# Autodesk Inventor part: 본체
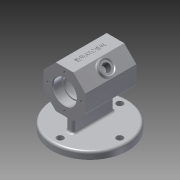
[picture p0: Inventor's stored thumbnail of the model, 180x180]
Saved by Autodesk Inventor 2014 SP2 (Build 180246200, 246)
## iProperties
Created: 2021-02
Part Number: 본체
Material: 알루미늄 6061
Document SubType Name: Modeling
Designer: 거성
Density: 2.71 g/cm^3
Appearance: 알루미늄 - 평지
Author: 거성
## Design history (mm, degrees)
sketch "스케치1"
  geometry: C1 r 52 at (0, 0); 1 further point
  constraints: 1 centre point, 1 coincident
  dimensions: "d0" = 104 diameter of C1
extrude "돌출1" new body sketch "스케치1" distance "d1" = 10; taper "d2" = 0 deg
sketch "스케치3"
  geometry: L1 (52, 10)-(-52, 10) reference; L2 (-52, 0)-(52, 0) reference; L3 (12.012, 33)-(-12.012, 33); L4 (-12.012, 33)-(-29, 49.988); L5 (-29, 49.988)-(-29, 74.012); L6 (-29, 74.012)-(-12.012, 91); L7 (-12.012, 91)-(12.012, 91); L8 (12.012, 91)-(29, 74.012); L9 (29, 74.012)-(29, 49.988); L10 (29, 49.988)-(12.012, 33); C1 r 29 at (0, 62); 3 further points
  constraints: 16 end point, 1 centre point, 1 coincident, 1 horizontal, 1 midpoint, 1 tangent, 1 vertical alignment, 17 other
  dimensions: "d12" = 58 diameter of C1; "d13" = 62 distance from line of L2 C1.centre
extrude "돌출2" join sketch "스케치3" stored distance "d14" = 70; taper "d15" = 0 deg
sketch "스케치4"
  geometry: L1 (49.988, 35)-(49.988, -35) reference; L2 (74.012, 35)-(49.988, 35) reference; L3 (74.012, 35)-(74.012, -35) reference; L4 (49.988, -35)-(74.012, -35) reference; L5 (74.012, 35)-(74.012, -35) reference; L6 (91, 35)-(74.012, 35) reference; L7 (91, 35)-(91, -35) reference; L8 (74.012, -35)-(91, -35) reference; L9 (33, 35)-(33, -35) reference; L10 (49.988, 35)-(33, 35) reference; L11 (49.988, 35)-(49.988, -35) reference; L12 (33, -35)-(49.988, -35) reference; L13 (10, -52)-(10, 52) reference; L14 (0, 52)-(0, -52) reference; L15 (62, 35)-(62, -35); L16 (62, 35)-(78, 35); L17 (78, 23)-(76, 23); L18 (76, 23)-(76, 20); L19 (76, 20)-(84, 20); L20 (84, 20)-(84, -20); L21 (84, -20)-(76, -20); L22 (76, -20)-(76, -23); L23 (76, -23)-(78, -23); L24 (78, -23)-(78, -35); L25 (78, 23)-(78, 35); L26 (78, -35)-(62, -35); 1 further point
  constraints: 24 end point, 4 collinear, 4 parallel, 3 perpendicular, 2 midpoint, 2 point on line, 1 horizontal
  dimensions: "d16" = 16 distance between parallel lines of L15 L25; "d17" = 3 distance between parallel lines of L19 L17; "d18" = 12 distance between parallel lines of L17 L16; "d19" = 14 distance between parallel lines of L15 L18; "d20" = 22 distance between parallel lines of L15 L20; "d21" = 40 distance between parallel lines of L21 L19; "d22" = 3 distance between parallel lines of L21 L23
revolve "회전1" sketch "스케치4" stored, may be unused: angle "d23" = 90 deg
sketch "스케치5"
  geometry: C1 r 52 at (0, 0) reference; C2 r 4.5 at (0, 41)
  constraints: 1 centre point, 1 vertical alignment
  dimensions: "d24" = 9 diameter of C2; "d25" = 41 distance of C1.centre C2.centre
extrude "돌출3" cut sketch "스케치5" stored distance "d26" = 70; taper "d27" = 0 deg
fillet "모깎기1" dims "d31" = 3
chamfer "모따기1" distance "d32" = 1; stored, may be unused: second distance "d33" = 2, angle "d34" = 45 deg
fillet "모깎기2" dims "d35" = 0.3
fillet "모깎기3" dims "d36" = 3
sketch "스케치6"
  geometry: C1 r 17 at (0, 62) reference; C2 r 2 at (0, 85); 1 further point
  constraints: 1 centre point, 1 vertical alignment
  dimensions: "d37" = 23 distance of C1.centre C2.centre; "d38" = 4 diameter of C2
hole "구멍1" sketch "스케치6" at (0, 85) diameter "d39" = 3.242; stored, may be unused: countersink angle "d43" = 90 deg, drill point angle "d45" = 118 deg; dims "d40" = 8, "d41" = 4, "d42" = 2, "d44" = 10
sketch "스케치7"
  geometry: L1 (24.024, 0)-(0, 0) reference; L2 (-16.988, 0)-(-16.988, 70) reference; 2 further points
  constraints: 1 other
  dimensions: "d49" = 29 distance from line of L2 point (12.012, 35); "d50" = 35 distance from line of L1 point (12.012, 35)
feature "엠보싱1" sketch "스케치7" dims "d1" = 10, "d2" = 0, "d51" = 0.5, "d52" = 0
sketch "스케치8"
  geometry: L1 (33, 35)-(33, -35) reference; L2 (49.988, 35)-(33, 35) reference; L3 (49.988, 35)-(49.988, -35) reference; L4 (33, -35)-(49.988, -35) reference; L5 (0, 52)-(0, -52) reference; L6 (7, -52)-(7, 52) reference; L7 (10, 49)-(10, -49) reference; L8 (7, -52)-(7, 52) reference; L9 (10, 49)-(10, -49) reference; L10 (33, 28)-(10, 28); L11 (10, 28)-(10, -28); L12 (10, -28)-(33, -28); L13 (33, -28)-(33, 28); 3 further points
  constraints: 8 end point, 2 collinear, 2 midpoint, 2 parallel, 1 horizontal, 1 horizontal alignment, 1 perpendicular
  dimensions: "d53" = 56 distance between parallel lines of L12 L10
extrude "돌출4" join sketch "스케치8" stored distance "d54" = 10; taper "d55" = 0 deg
fillet "모깎기4" dims "d56" = 3
fillet "모깎기5" dims "d57" = 3
sketch "스케치9"
  geometry: L1 (16.988, 70)-(16.988, 0) reference; C1 r 10 at (-12.012, 35); 1 further point
  constraints: 1 centre point, 1 horizontal alignment
  dimensions: "d58" = 20 diameter of C1; "d59" = 29 distance from line of L1 C1.centre
extrude "돌출5" join sketch "스케치9" distance "d60" = 5; taper "d61" = 0 deg
fillet "모깎기6" dims "d62" = 1
hole "구멍2" diameter "d65" = 10.917; stored, may be unused: countersink angle "d69" = 90 deg, drill point angle "d71" = 118 deg; dims "d66" = 21, "d67" = 16, "d68" = 2, "d70" = 21.25, "d72" = 10, "d73" = 10
chamfer "모따기2" distance "d75" = 1; stored, may be unused: second distance "d76" = 2, angle "d77" = 45 deg
fillet "모깎기8" dims "d78" = 1
node "솔리드1"
pattern_circular "원형 패턴1" dims angle "d29" = 360 deg
pattern_circular "원형 패턴2" dims angle "d47" = 360 deg
mirror "대칭1"
node "투영된 루프2"
node "투영된 루프3"
node "투영된 루프4"
node "투영된 루프5"
node "투영된 루프6"
node "투영된 루프7"
node "투영된 루프8"
node "투영된 루프9"
